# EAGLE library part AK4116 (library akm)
Digital Audio Receiver (DIR) Low Power, 24-Bit, 48 kHz
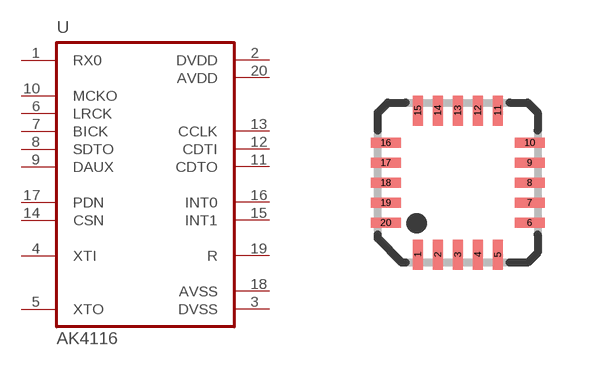
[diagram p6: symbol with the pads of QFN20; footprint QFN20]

Designator prefix U

## AK4116  [QFN20]
1  RX0  in
2  DVDD  pwr
3  DVSS  pwr
4  XTI  in
5  XTO  out
6  LRCK  out
7  BICK  out
8  SDTO  out
9  DAUX  in
10  MCKO  out
11  CDTO  out
12  CDTI  in
13  CCLK  in
14  CSN  in
15  INT1  out
16  INT0  out
17  PDN  in
18  AVSS  pwr
19  R  pas
20  AVDD  pwr

## Footprint QFN20 (pad centres in mm)
QFN20 4x4 mm, pitch 0.5 mm
smd 0.25 x 0.75: 1 -1,-1.8; 2 -0.5,-1.8; 3 0,-1.8; 4 0.5,-1.8; 5 1,-1.8; 11 1,1.8; 12 0.5,1.8; 13 0,1.8; 14 -0.5,1.8; 15 -1,1.8
smd 0.75 x 0.25: 6 1.8,-1; 7 1.8,-0.5; 8 1.8,0; 9 1.8,0.5; 10 1.8,1; 16 -1.8,1; 17 -1.8,0.5; 18 -1.8,0; 19 -1.8,-0.5; 20 -1.8,-1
